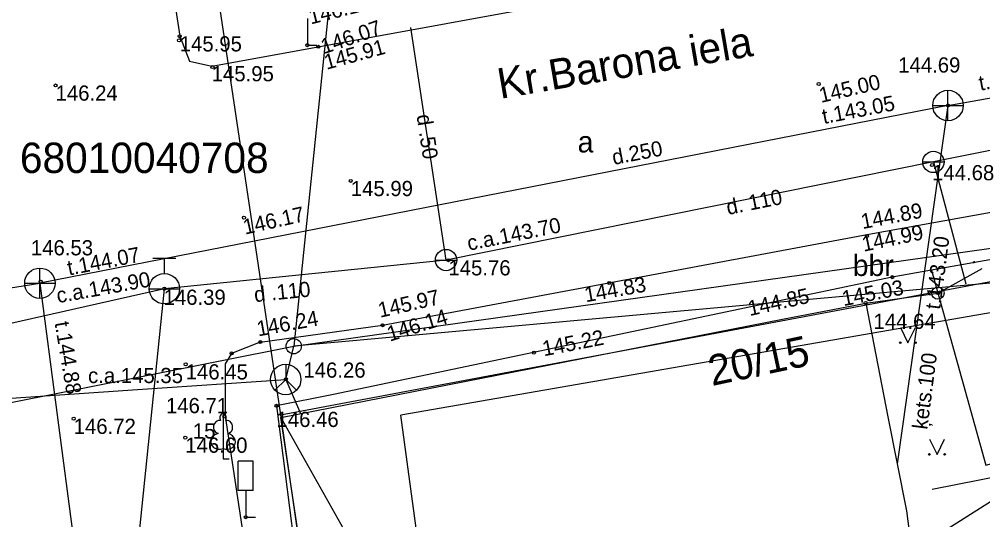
# Model space of a CAD drawing. Extents: x 728492 to 729038, y 272968 to 273171.
# Drawn here: x 728668.45 to 728700.13, y 273065.2 to 273081.67 of the extents above; entities that cross this region are included whole.
import ezdxf

# ---------------------------------------------------------------- set-up
doc = ezdxf.new("R2010")
doc.units = 0
for name, color, linetype in [('APGR_SARK_####_####_#', 7, 'Continuous'), ('BUVE_BDET_####_####_#', 7, 'Continuous'), ('BUVE_EKAS_####_####_#', 7, 'Continuous'), ('BUVE_EKAS_ADRS_TKST_#', 7, 'Continuous'), ('CELI_CAPM_####_####_#', 7, 'Continuous'), ('CELI_CMAL_####_####_#', 7, 'Continuous'), ('CELI_CSEG_####_TKST_#', 7, 'Continuous'), ('CELI_ELEM_####_####_#', 7, 'Continuous'), ('CELI_IELA_####_TKST_#', 7, 'Continuous'), ('CELI_SEGL_####_####_#', 7, 'Continuous'), ('NORB_ELEM_####_####_#', 7, 'Continuous'), ('NORB_ZOGS_BARJ_####_#', 7, 'Continuous'), ('NORB_ZOGS_KOKA_####_#', 7, 'Continuous'), ('RAMI_UZMR_####_####_#', 7, 'Continuous'), ('RELJ_AATZ_####_TKST_#', 7, 'Continuous'), ('RELJ_ELEM_####_####_#', 7, 'Continuous'), ('ROBZ_KADS_####_TKST_#', 7, 'Continuous'), ('ROBZ_UZMR_####_####_#', 7, 'Continuous'), ('SAKK_ELEM_####_####_#', 7, 'Continuous'), ('SAKK_ELEM_####_TKST_#', 7, 'Continuous'), ('SAKK_KKAN_####_####_#', 7, 'Continuous'), ('SAKK_KKAN_####_TKST_#', 7, 'Continuous'), ('SAKT_ELEM_####_####_#', 7, 'Continuous'), ('SAKT_STUT_####_####_#', 7, 'Continuous'), ('SAKT_VADV_KLIN_####_#', 7, 'Continuous'), ('SAKT_VADV_PKAB_####_#', 7, 'Continuous'), ('SKAN_ELEM_####_####_#', 7, 'Continuous'), ('SKAN_VADP_PAST_####_#', 7, 'Continuous'), ('SKAN_VADP_PAST_TKST_#', 7, 'Continuous'), ('TERT_DIAM_####_TKST_#', 7, 'Continuous'), ('TERT_ELEM_####_####_#', 7, 'Continuous'), ('UDTK_ELEM_####_####_#', 7, 'Continuous'), ('UDTK_ELEM_####_TKST_#', 7, 'Continuous'), ('UDTK_VADP_UDEN_####_#', 7, 'Continuous'), ('UDTK_VADP_UDEN_TKST_#', 7, 'Continuous')]:
    doc.layers.add(name, color=color, linetype=linetype)

msp = doc.modelspace()

# ---------------------------------------------------------------- linework, layer by layer
at = {"layer": 'APGR_SARK_####_####_#'}
for points in [[(728815.186, 273091.969), (728680.999, 273068.647)], [(728684.022, 273046.348), (728680.999, 273068.647)]]:
    msp.add_lwpolyline(points, dxfattribs=at)
at = {"layer": 'BUVE_BDET_####_####_#'}
msp.add_lwpolyline([(728677.051, 273068.571), (728679.223, 273064.706)], dxfattribs=at)
at = {"layer": 'BUVE_EKAS_####_####_#'}
for p, q in [((728693.552, 273071.8), (728696.285, 273072.335)), ((728696.285, 273072.335), (728697.017, 273068.594)), ((728677.051, 273068.571), (728693.552, 273071.8)), ((728678.601, 273058.219), (728677.051, 273068.571)), ((728697.017, 273068.594), (728697.622, 273065.502)), ((728697.622, 273065.502), (728697.893, 273063.412))]:
    msp.add_line(p, q, dxfattribs=at)
at = {"layer": 'CELI_CAPM_####_####_#'}
for p, q in [((728673.724, 273081.115), (728674.047, 273080.299)), ((728674.047, 273080.299), (728674.775, 273080.133))]:
    msp.add_line(p, q, dxfattribs=at)
for points in [[(728676.374, 273071.049), (728680.397, 273071.606), (728696.384, 273074.602), (728721.076, 273079.042), (728739.743, 273082.405), (728759.114, 273085.751), (728811.654, 273095.023), (728814.654, 273095.178), (728815.22, 273095.032), (728815.785, 273094.657), (728816.384, 273093.154), (728816.384, 273093.154), (728817.477, 273084.163), (728819.159, 273072.476)], [(728674.775, 273080.133), (728674.775, 273080.133), (728693.992, 273083.644), (728719.252, 273088.265), (728737.995, 273091.64)], [(728672.307, 273089.605), (728672.856, 273086.761), (728673.724, 273081.115)], [(728676.374, 273071.049), (728675.428, 273070.679), (728675.22, 273070.334), (728675.222, 273068.615), (728676.716, 273058.658)]]:
    msp.add_lwpolyline(points, dxfattribs=at)
at = {"layer": 'CELI_CMAL_####_####_#'}
for p, q in [((728698.448, 273073.418), (728697.157, 273073.187)), ((728697.157, 273073.187), (728678.777, 273069.324)), ((728678.777, 273069.324), (728676.907, 273068.954)), ((728676.907, 273068.954), (728678.26, 273058.341))]:
    msp.add_line(p, q, dxfattribs=at)
msp.add_lwpolyline([(728698.448, 273073.418), (728700.24, 273067.002), (728703.335, 273067.866), (728701.721, 273074.002)], dxfattribs=at)
at = {"layer": 'CELI_ELEM_####_####_#'}
for p, q in [((728677.921, 273081.699), (728677.921, 273080.821)), ((728677.921, 273080.821), (728678.236, 273080.821)), ((728676.142, 273067.134), (728675.642, 273067.134)), ((728675.642, 273066.165), (728675.642, 273067.134)), ((728676.142, 273066.165), (728676.142, 273067.134)), ((728676.142, 273066.165), (728675.642, 273066.165)), ((728675.896, 273066.165), (728675.896, 273065.287)), ((728675.896, 273065.287), (728676.211, 273065.287))]:
    msp.add_line(p, q, dxfattribs=at)
at = {"layer": 'CELI_SEGL_####_####_#'}
msp.add_line((728701.721, 273074.002), (728698.448, 273073.418), dxfattribs=at)
at = {"layer": 'NORB_ELEM_####_####_#'}
msp.add_circle((728698.659, 273072.664), 0.202, dxfattribs=at)
at = {"layer": 'NORB_ZOGS_BARJ_####_#'}
msp.add_lwpolyline([(728698.659, 273072.664), (728700.11, 273073.473)], dxfattribs=at)
at = {"layer": 'NORB_ZOGS_KOKA_####_#'}
msp.add_lwpolyline([(728696.285, 273072.335), (728698.659, 273072.664)], dxfattribs=at)
at = {"layer": 'RAMI_UZMR_####_####_#'}
msp.add_lwpolyline([(728545.121, 273067.256), (728525.538, 273066.106), (728511.145, 273059.016), (728527.731, 273033.328), (728550.271, 273033.197), (728572.013, 273034.886), (728580.562, 273045.27), (728653.673, 273058.931), (728671.713, 273053.291), (728688.721, 273058.407), (728702.149, 273066.922)], dxfattribs=at)
at = {"layer": 'RELJ_ELEM_####_####_#'}
for centre in [(728673.701, 273080.982), (728673.724, 273081.115), (728677.921, 273080.821), (728677.921, 273080.821), (728678.285, 273080.768), (728674.801, 273080.101), (728669.64, 273079.495), (728694.738, 273079.542), (728698.991, 273078.836), (728698.468, 273076.876), (728679.35, 273076.354), (728675.836, 273075.146), (728696.326, 273074.537), (728682.561, 273073.745), (728669.151, 273073.042), (728697.157, 273073.187), (728673.219, 273072.807), (728687.85, 273072.997), (728698.659, 273072.664), (728696.285, 273072.335), (728680.397, 273071.606), (728676.374, 273071.049), (728675.428, 273070.679), (728685.371, 273070.703), (728673.92, 273070.32), (728677.215, 273069.828), (728676.907, 273068.954), (728675.194, 273068.604), (728670.236, 273068.528), (728673.906, 273067.907), (728675.896, 273065.287), (728675.896, 273065.287)]:
    msp.add_circle(centre, 0.05, dxfattribs=at)
at = {"layer": 'ROBZ_UZMR_####_####_#'}
for p, q in [((728675.015, 273082.231), (728677.033, 273068.656)), ((728677.033, 273068.656), (728721.926, 273077.099)), ((728677.033, 273068.656), (728679.337, 273052.938))]:
    msp.add_line(p, q, dxfattribs=at)
at = {"layer": 'SAKK_ELEM_####_####_#'}
msp.add_line((728677.209, 273069.82), (728677.563, 273069.466), dxfattribs=at)
msp.add_lwpolyline([(728677.209, 273070.32), (728677.209, 273069.82), (728676.855, 273069.466)], dxfattribs=at)
msp.add_circle((728677.209, 273069.82), 0.5, dxfattribs=at)
at = {"layer": 'SAKK_KKAN_####_####_#'}
for q in [(728677.472, 273070.914), (728677.693, 273068.697)]:
    msp.add_line((728677.209, 273069.82), q, dxfattribs=at)
msp.add_lwpolyline([(728666.097, 273069.067), (728672.335, 273069.49), (728677.209, 273069.82)], dxfattribs=at)
at = {"layer": 'SAKT_ELEM_####_####_#'}
msp.add_circle((728677.472, 273070.914), 0.25, dxfattribs=at)
at = {"layer": 'SAKT_STUT_####_####_#'}
msp.add_line((728704.68, 273073.384), (728677.472, 273070.914), dxfattribs=at)
at = {"layer": 'SAKT_VADV_KLIN_####_#'}
msp.add_lwpolyline([(728677.472, 273070.914), (728725.843, 273077.714)], dxfattribs=at)
at = {"layer": 'SAKT_VADV_PKAB_####_#'}
for p in [(728678.992, 273085.631), (728635.134, 273062.502)]:
    msp.add_line(p, (728677.472, 273070.914), dxfattribs=at)
at = {"layer": 'SKAN_ELEM_####_####_#'}
for p, q in [((728698.991, 273078.336), (728698.991, 273079.336)), ((728698.491, 273078.836), (728699.491, 273078.836)), ((728669.124, 273072.487), (728669.124, 273073.487)), ((728668.624, 273072.987), (728669.624, 273072.987))]:
    msp.add_line(p, q, dxfattribs=at)
for centre in [(728698.991, 273078.836), (728669.124, 273072.987)]:
    msp.add_circle(centre, 0.5, dxfattribs=at)
at = {"layer": 'SKAN_VADP_PAST_####_#'}
for p, q in [((728698.991, 273078.836), (728669.124, 273072.987)), ((728669.124, 273072.987), (728670.474, 273062.714))]:
    msp.add_line(p, q, dxfattribs=at)
for points in [[(728698.991, 273078.836), (728720.316, 273082.646), (728716.486, 273077.576), (728718.007, 273069.977)], [(728698.991, 273078.836), (728697.32, 273067.048)], [(728616.534, 273064.605), (728669.124, 273072.987)]]:
    msp.add_lwpolyline(points, dxfattribs=at)
at = {"layer": 'TERT_ELEM_####_####_#'}
for p, q in [((728697.424, 273071.531), (728697.674, 273071.031)), ((728697.674, 273071.031), (728697.924, 273071.531)), ((728698.38, 273067.855), (728698.63, 273067.355)), ((728698.63, 273067.355), (728698.88, 273067.855)), ((728675.15, 273067.551), (728675.15, 273067.204)), ((728675.15, 273067.204), (728675.35, 273067.204))]:
    msp.add_line(p, q, dxfattribs=at)
for points in [[(728675.15, 273068.704), (728675.15, 273067.551)], [(728675.24, 273068.472), (728675.239, 273068.473)]]:
    msp.add_lwpolyline(points, dxfattribs=at)
for centre, radius in [((728697.423, 273071.031), 0.028), ((728697.923, 273071.031), 0.0263), ((728698.379, 273067.354), 0.028), ((728698.879, 273067.354), 0.0263)]:
    msp.add_circle(centre, radius, dxfattribs=at)
for centre, major_axis, ratio, start_param, end_param in [((728675.15, 273068.555), (0, -0.15), 0.707107, 3.14537, 5.287485), ((728675.15, 273068.555), (0, -0.15), 0.707107, 0.995701, 3.137816), ((728675.022, 273068.26), (-0.039, -0.212), 0.861323, 3.141593, 6.283185), ((728675.278, 273068.26), (0.039, -0.212), 0.861323, 0, 3.141593), ((728675.06, 273067.797), (0.307, 0.095), 0.814445, 1.570796, 4.752015), ((728675.24, 273067.797), (-0.307, 0.095), 0.814445, 1.531171, 4.712389)]:
    msp.add_ellipse(centre, major_axis=major_axis, ratio=ratio, start_param=start_param, end_param=end_param, dxfattribs=at)
at = {"layer": 'UDTK_ELEM_####_####_#'}
for p, q in [((728698.161, 273076.977), (728698.863, 273076.977)), ((728698.511, 273076.977), (728698.511, 273076.978)), ((728672.843, 273073.807), (728673.593, 273073.807)), ((728673.218, 273073.307), (728673.218, 273073.807)), ((728682.131, 273073.751), (728682.833, 273073.751)), ((728682.481, 273073.751), (728682.481, 273073.752)), ((728672.719, 273072.807), (728673.719, 273072.807))]:
    msp.add_line(p, q, dxfattribs=at)
for centre, radius in [((728698.512, 273076.977), 0.351), ((728682.482, 273073.751), 0.351), ((728673.218, 273072.807), 0.5), ((728673.219, 273072.807), 0.5)]:
    msp.add_circle(centre, radius, dxfattribs=at)
at = {"layer": 'UDTK_VADP_UDEN_####_#'}
for p, q in [((728682.482, 273073.751), (728681.324, 273081.405)), ((728698.512, 273076.977), (728682.482, 273073.751)), ((728698.512, 273076.977), (728699.58, 273072.967)), ((728682.482, 273073.751), (728673.218, 273072.807)), ((728673.219, 273072.807), (728657.437, 273069.243)), ((728672.055, 273061.416), (728673.218, 273072.807)), ((728705.829, 273067.642), (728698.468, 273066.202))]:
    msp.add_line(p, q, dxfattribs=at)
msp.add_lwpolyline([(728714.148, 273079.76), (728711.204, 273079.532), (728698.512, 273076.977)], dxfattribs=at)

# ---------------------------------------------------------------- texts
at = {"layer": 'BUVE_EKAS_ADRS_TKST_#'}
msp.add_text('20/15', height=1, rotation=12, dxfattribs=at).set_placement((728691.227, 273069.603))
at = {"layer": 'CELI_CSEG_####_TKST_#'}
for s, p in [('a', (728686.81, 273077.291)), ('bbr', (728695.856, 273073.225))]:
    msp.add_text(s, height=0.7, dxfattribs=at).set_placement(p)
at = {"layer": 'CELI_IELA_####_TKST_#'}
msp.add_text('Kr.Barona iela', height=1, rotation=9.638, dxfattribs=at).set_placement((728684.265, 273079.053))
at = {"layer": 'CELI_SEGL_####_####_#'}
msp.add_text('.', height=0.5, rotation=284.9136, dxfattribs=at).set_placement((728699.783, 273073.757))
at = {"layer": 'RELJ_AATZ_####_TKST_#'}
for s, rotation, p in [('146.10', 14.1646, (728678.035, 273081.502)), ('146.07', 18.9391, (728678.468, 273080.524)), ('145.91', 15.2671, (728678.551, 273080.01)), ('145.00', 13.2296, (728694.815, 273078.92)), ('144.89', 10.8226, (728696.18, 273074.768)), ('146.17', 12.7097, (728675.868, 273074.585)), ('144.99', 11.8029, (728696.214, 273074.022)), (' 144.83', 10.0513, (728686.897, 273072.328)), ('145.03', 10.8943, (728695.556, 273072.232)), ('145.97', 12.7814, (728680.311, 273071.85)), (' 144.85', 12.5407, (728692.29, 273071.865)), ('146.14', 17.4607, (728680.633, 273071.063)), ('146.24', 10.3132, (728676.304, 273071.236)), (' 145.22', 11.0452, (728685.518, 273070.546))]:
    msp.add_text(s, height=0.5, rotation=rotation, dxfattribs=at).set_placement(p)
for s, p in [('145.95', (728673.724, 273080.615)), ('145.95', (728674.775, 273079.633)), ('146.24', (728669.64, 273078.995)), ('145.99', (728679.35, 273075.854)), (' 144.64', (728696.355, 273071.484)), ('146.45', (728673.92, 273069.82)), ('146.71', (728673.271, 273068.711)), ('146.46', (728676.907, 273068.256)), ('146.72', (728670.236, 273068.028)), ('146.60', (728673.906, 273067.407))]:
    msp.add_text(s, height=0.5, dxfattribs=at).set_placement(p)
at = {"layer": 'ROBZ_KADS_####_TKST_#'}
msp.add_text('68010040708', height=1, dxfattribs=at).set_placement((728668.467, 273076.615))
at = {"layer": 'SAKK_ELEM_####_TKST_#'}
msp.add_text(' 146.26', height=0.5, dxfattribs=at).set_placement((728677.606, 273069.879))
at = {"layer": 'SAKK_KKAN_####_TKST_#'}
msp.add_text('c.a.145.35', height=0.5, dxfattribs=at).set_placement((728670.709, 273069.701))
at = {"layer": 'SKAN_ELEM_####_####_#'}
for s, p in [('144.69', (728697.353, 273079.92)), ('146.53', (728668.828, 273073.905))]:
    msp.add_text(s, height=0.5, dxfattribs=at).set_placement(p)
at = {"layer": 'SKAN_VADP_PAST_TKST_#'}
for s, rotation, p in [('t.143.03', 10.13, (728700.052, 273079.322)), ('t.143.05', 10.955, (728694.905, 273078.226)), ('d.250', 10.955, (728687.995, 273076.879)), ('t.143.20', 82.671, (728698.732, 273072.104)), ('t.144.07', 10.955, (728670.079, 273073.24)), ('t.144.88', 279.524, (728669.607, 273071.686)), ('ķets.100', 82.671, (728698.309, 273068.156))]:
    msp.add_text(s, height=0.5, rotation=rotation, dxfattribs=at).set_placement(p)
at = {"layer": 'TERT_DIAM_####_TKST_#'}
msp.add_text('15', height=0.5, dxfattribs=at).set_placement((728674.156, 273067.877))
at = {"layer": 'UDTK_ELEM_####_TKST_#'}
for s, p in [('144.68', (728698.468, 273076.376)), ('145.76', (728682.561, 273073.245)), ('146.39', (728673.192, 273072.276))]:
    msp.add_text(s, height=0.5, dxfattribs=at).set_placement(p)
at = {"layer": 'UDTK_VADP_UDEN_TKST_#'}
for s, rotation, p in [('d .50', 278.6032, (728681.51, 273078.509)), ('d. 110', 11.3787, (728691.753, 273075.233)), ('c.a.143.70', 11.3787, (728683.231, 273074.055)), ('c.a.143.90', 10.198, (728669.716, 273072.33)), ('d .110', 5.8183, (728676.195, 273072.364))]:
    msp.add_text(s, height=0.5, rotation=rotation, dxfattribs=at).set_placement(p)

doc.saveas('drawing.dxf')
